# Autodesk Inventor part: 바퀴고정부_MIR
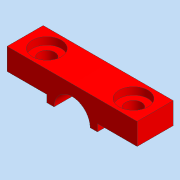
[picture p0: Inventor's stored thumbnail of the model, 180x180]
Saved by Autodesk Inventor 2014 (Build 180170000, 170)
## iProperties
Created: 2015-05
Part Number: 바퀴고정부_MIR
Material: 일반
Vendor: CBT Solutions
Document SubType Name: 모델링
Designer: Administrator
Appearance: 기본값
Company: 한국ATC센터
Author: KYOUNG IL JANG
Comments: 파생
d0: 1.000 ul
d0_1: 1.000 ul
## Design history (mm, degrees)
derived "바퀴고정부.ipt" dims count "d0" = 1
feature "솔리드1::바퀴고정부.ipt" dims count "d0" = 1
tag "피쳐 태그1"
node "솔리드1"
other parameters: "d0_1" = 1
